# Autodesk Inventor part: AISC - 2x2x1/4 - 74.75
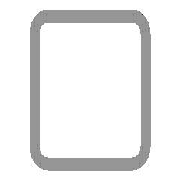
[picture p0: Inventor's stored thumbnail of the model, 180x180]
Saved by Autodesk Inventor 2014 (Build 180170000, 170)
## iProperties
IsCustomPart: 1
Created: 2013-02
Part Number: AISC - 2x2x1/4 - 74.75
Material: Steel, Mild
Description: Tube
Document SubType Name: Modeling
Standard: AISC
Designer: Dave Walker
Standards Organization: ANSI
Language: en-US
Size Designation: 2x2x1/4 - 74.75
Categories: <MemberInstance><Categories><Category DisplayName="Structural Shapes" InternalName="089c4875-fa83-4c05-b084-43b9cc11f5ed" Mnemonic="GRDR"><CategoryParameter Dis
Stock Number: 2x2x1/4
Density: 1 g/cm^3
Appearance: Steel
G_L: 74.750 in
Author: Dave Walker
Title: Subframe Side Tube
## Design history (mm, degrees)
node "Start plane"
node "End plane"
sketch "Sketch"
  geometry: L1 (-25.4, -12.7)-(-25.4, 12.7); L2 (-12.7, 25.4)-(12.7, 25.4); L3 (25.4, 12.7)-(25.4, -12.7); L4 (12.7, -25.4)-(-12.7, -25.4); L5 (-12.7, 19.05)-(12.7, 19.05); L6 (19.05, 12.7)-(19.05, -12.7); L7 (12.7, -19.05)-(-12.7, -19.05); L8 (-19.05, -12.7)-(-19.05, 12.7); L9 (0, 36.948)-(0, -36.948) reference; L10 (-23.079, 0)-(23.079, 0) reference; A1 r 12.7 centre (-12.7, -12.7) between (-25.4, -12.7) and (-12.7, -25.4); A2 r 12.7 centre (-12.7, 12.7) between (-12.7, 25.4) and (-25.4, 12.7); A3 r 12.7 centre (12.7, 12.7) between (25.4, 12.7) and (12.7, 25.4); A4 r 12.7 centre (12.7, -12.7) between (12.7, -25.4) and (25.4, -12.7); A5 r 6.35 centre (-12.7, 12.7) between (-12.7, 19.05) and (-19.05, 12.7); A6 r 6.35 centre (12.7, 12.7) between (19.05, 12.7) and (12.7, 19.05); A7 r 6.35 centre (12.7, -12.7) between (12.7, -19.05) and (19.05, -12.7); A8 r 6.35 centre (-12.7, -12.7) between (-19.05, -12.7) and (-12.7, -19.05)
  constraints: 16 end point, 16 point on circle, 8 centre point, 8 tangent, 4 parallel, 3 equal radius, 2 perpendicular, 7 other
  dimensions: "d10" = 50.8 distance between parallel lines of L2 L4 (= G_H); "d11" = 50.8 distance between parallel lines of L1 L3 (= G_W); "d12" = 6.35 distance between parallel lines of L3 L6 (= G_T); "d15" = 25.4 distance between parallel lines of L2 L10 (= 0.5 x d10); "d16" = 25.4 distance between parallel lines of L9 L3 (= 0.5 x d11); "d17" = 12.7 radius of A1 (= G_IR)
extrude "Body" new body sketch "Sketch" stored distance "d3" = 1898.65 (= G_L); taper "d4" = 0 deg
node "Driven Length"
  sketch "Sketch3"
    geometry: L1 (0, 0)-(10, 0) reference
    constraints: 2 end point, 1 horizontal
  workplane "Work Plane3"
  sketch "Sketch4"
    geometry: L1 (-2, 0)-(12, 0) reference; L2 (-2, 1898.65)-(12, 1898.65) reference
    dimensions: "d19" = 1898.65 distance between parallel lines of L1 L2 (derived)
body "Solid1"
other parameters: "G_W" = 50.8 [user parameter; used in 1 equation term], "G_H" = 50.8 [user parameter; used in 1 equation term], "G_T" = 6.35 [user parameter; used in 1 equation term], "G_IR" = 12.7 [user parameter; used in 1 equation term], "G_L" = 1898.65 (= d19) [user parameter; used in 1 equation term], "G_OFFSET_START" = 0 [user parameter; used in 1 equation term], "G_OFFSET_END" = 0 [user parameter; used in 1 equation term], "d13" = 0 (computed from G_OFFSET_START), "d14" = 1898.65 (= G_OFFSET_END + B_L), "B_L" = 1898.65 [user parameter; used in 1 equation term], "d18" = 90 deg
